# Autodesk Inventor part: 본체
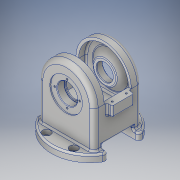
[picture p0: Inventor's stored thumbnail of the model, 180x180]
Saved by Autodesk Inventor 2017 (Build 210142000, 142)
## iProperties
Part Number: 본체
Material: 알루미늄 6061
Document SubType Name: Modeling
Designer: MRC
Density: 2.7 g/cm^3
Appearance: 알루미늄 - 평지
Mass: 1198.45 g
Surface Area: 1058.11 cm^2
Volume: 443.871 cm^3
Author: MRC
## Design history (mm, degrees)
sketch "스케치1"
  geometry: C1 r 71 at (0, 0); 1 further point
  constraints: 1 centre point, 1 coincident
  dimensions: "d0" = 142 diameter of C1
extrude "돌출1" new body sketch "스케치1" distance "d1" = 13; taper "d2" = 0 deg
sketch "스케치2"
  geometry: L1 (-71, 0)-(71, 0) reference; L2 (-51, 81)-(-51, 0); L3 (51, 81)-(51, 0); L4 (-51, 0)-(51, 0); A1 r 51 centre (0, 81) between (-51, 81) and (51, 81); 1 further point
  constraints: 6 end point, 2 point on circle, 2 point on line, 2 tangent, 1 centre point, 1 horizontal, 1 parallel, 1 perpendicular, 1 vertical alignment
  dimensions: "d3" = 102 diameter of A1; "d4" = 81 distance from line of A1.centre L1
extrude "돌출2" join sketch "스케치2" stored distance "d5" = 88; taper "d6" = 0 deg
node "작업 평면1"
sketch "스케치4"
  geometry: L1 (61, -20)-(-61, -20); L2 (-61, -20)-(-61, 20); L3 (-61, 20)-(61, 20); L4 (61, 20)-(61, -20); L5 (61, -20)-(-61, 20); L6 (-61, -20)-(61, 20); 1 further point
  constraints: 12 end point, 2 midpoint, 2 parallel, 1 horizontal, 1 perpendicular
  dimensions: "d10" = 40 distance of L3.end L1.start; "d11" = 122 distance of L1.start L1.end
extrude "돌출3" join sketch "스케치4" distance "d12" = 20; taper "d13" = 0 deg
sketch "스케치5"
  geometry: L1 (-89.487, -28)-(89.487, -28); L2 (89.487, -28)-(89.487, 28); L3 (89.487, 28)-(-89.487, 28); L4 (-89.487, 28)-(-89.487, -28); L5 (-89.487, -28)-(89.487, 28); L6 (89.487, -28)-(-89.487, 28); 1 further point
  constraints: 12 end point, 2 midpoint, 2 parallel, 1 horizontal, 1 perpendicular
  dimensions: "d14" = 56 distance of L1.end L2.end; "d15" = 178.97487 distance of L2.end L3.end
extrude "돌출4" cut sketch "스케치5" distance "d16" = 19; taper "d17" = 0 deg
sketch "스케치6"
  geometry: L1 (-51, 13)-(51, 13) reference; L2 (-51, 13)-(-51, 81) reference; L3 (51, 81)-(51, 13) reference; L4 (-46, 81)-(-46, 40); L5 (46, 40)-(46, 81); L6 (65.246, 0)-(-65.246, 0) reference; L7 (-46, 40)-(46, 40); A1 r 51 centre (0, 81) between (51, 81) and (-51, 81) reference; A2 r 46 centre (0, 81) between (46, 81) and (-46, 81); 1 further point
  constraints: 6 end point, 2 point on circle, 1 centre point, 1 horizontal
  dimensions: "d18" = 5 radial gap between concentric circles of A1 A2; "d20" = 5 distance between parallel lines of L3 L5; "d21" = 5 distance between parallel lines of L2 L4; "d22" = 40 distance between parallel lines of L6 L7
extrude "돌출5" cut sketch "스케치6" stored distance "d23" = 78; taper "d24" = 0 deg
sketch "스케치7"
  geometry: L1 (201.818, -25)-(81, -25); L2 (81, -25)-(81, 25); L3 (81, 25)-(201.818, 25); L4 (201.818, 25)-(201.818, -25); L5 (0, 71)-(0, 28) reference; 2 further points
  constraints: 8 end point, 2 parallel, 1 horizontal, 1 horizontal alignment, 1 midpoint, 1 perpendicular
  dimensions: "d25" = 50 distance of L3.end L1.start; "d26" = 81 distance between parallel lines of L2 L5; "d27" = 120.81817 distance of L2.end L3.end
extrude "돌출6" cut sketch "스케치7" stored distance "d28" = 78; taper "d29" = 0 deg
sketch "스케치8"
  geometry: L1 (81, -25)-(81, 25) reference; L2 (81, -44)-(81, -25) reference; L3 (13, 44)-(81, 44) reference; L4 (81, -44)-(13, -44) reference; L5 (81, -44)-(132, -44) reference; L6 (132, 44)-(81, 44) reference; L7 (81, 25)-(81, 39) reference; L8 (81, -44)-(81, 44); L9 (102.5, -27)-(81, -27); L10 (81, -39)-(127, -39) reference; L11 (102.5, -27)-(114.5, -39); L12 (81, -39)-(114.5, -39); L13 (127, -39)-(127, -25) reference; L14 (81, -39)-(40, -39) reference; L15 (81, -39)-(81, -27); 1 further point
  constraints: 10 end point, 2 point on line, 1 collinear, 1 horizontal, 1 perpendicular, 1 vertical
  dimensions: "d30" = 12 horizontal distance of L9.start L11.end; "d31" = 45 deg angle of L11 L13; "d32" = 67 diameter of L11.end L2
revolve "회전1" sketch "스케치8" stored, may be unused: angle "d33" = 90 deg
sketch "스케치9"
  geometry: L1 (-65.246, 0)-(65.246, 0) reference; C1 r 30 at (0, 81); 2 further points
  constraints: 1 centre point, 1 midpoint, 1 vertical alignment
  dimensions: "d34" = 60 diameter of C1; "d35" = 81 distance from line of C1.centre L1
extrude "돌출7" cut sketch "스케치9" distance "d36" = 2; taper "d37" = 0 deg
sketch "스케치10"
  geometry: C1 r 30 at (0, 0) reference; C2 r 21.5 at (0, 0) reference; C3 r 18.5 at (0, 0); 1 further point
  constraints: 1 centre point, 1 coincident
  dimensions: "d38" = 37 diameter of C3
extrude "돌출8" cut sketch "스케치10" distance "d39" = 13; taper "d40" = 0 deg
sketch "스케치11"
  geometry: C1 r 30 at (0, 0) reference; C2 r 16 at (0, 0); 1 further point
  constraints: 1 centre point, 1 coincident
  dimensions: "d41" = 32 diameter of C2
extrude "돌출9" cut sketch "스케치11" distance "d42" = 13; taper "d43" = 0 deg
sketch "스케치12"
  geometry: C1 r 16 at (0, 0) reference; A1 r 23 centre (0, 0) between (23, 0) and (0, 23); 3 further points
  constraints: 4 point on circle, 2 horizontal alignment, 2 vertical alignment, 1 centre point, 1 coincident
  dimensions: "d44" = 46 diameter of A1
hole "구멍1" sketch "스케치12" at (23, 0), (0, 23), (-23, 0), (0, -23) diameter "d45" = 3.242; stored, may be unused: countersink angle "d49" = 90 deg, drill point angle "d51" = 118 deg; dims "d46" = 8, "d47" = 4, "d48" = 2, "d50" = 10
sketch "스케치13"
  geometry: L1 (54, 13)-(-54, 13); L2 (-54, 13)-(-54, -13); L3 (-54, -13)-(54, -13); L4 (54, -13)-(54, 13); L5 (54, 13)-(-54, -13); L6 (-54, 13)-(54, -13); 5 further points
  constraints: 12 end point, 4 coincident, 2 midpoint, 2 parallel, 1 horizontal, 1 perpendicular
  dimensions: "d52" = 26 distance of L3.end L1.start; "d53" = 108 distance of L2.end L3.end
hole "구멍2" sketch "스케치13" at (54, 13), (54, -13), (-54, -13), (-54, 13) diameter "d54" = 3.242; stored, may be unused: countersink angle "d58" = 90 deg, drill point angle "d60" = 118 deg; dims "d55" = 8, "d56" = 4, "d57" = 2, "d59" = 10
sketch "스케치15"
  geometry: C1 r 30 at (0, 0); 1 further point
  constraints: 1 centre point, 1 coincident
  dimensions: "d69" = 60 diameter of C1
extrude "돌출10" cut sketch "스케치15" distance "d70" = 22; taper "d71" = 0 deg
sketch "스케치16"
  geometry: C1 r 14 at (0, 0); 1 further point
  constraints: 1 centre point, 1 coincident
  dimensions: "d72" = 28 diameter of C1
extrude "돌출11" cut sketch "스케치16" distance "d73" = 15; taper "d74" = 0 deg
sketch "스케치17"
  geometry: C1 r 11 at (0, 0); 1 further point
  constraints: 1 centre point, 1 coincident
  dimensions: "d75" = 22 diameter of C1
extrude "돌출12" cut sketch "스케치17" stored distance "d76" = 15; taper "d77" = 0 deg
sketch "스케치18"
  geometry: A1 r 23 centre (0, 0) between (23, 0) and (0, 23); 3 further points
  constraints: 4 point on circle, 2 horizontal alignment, 2 vertical alignment, 1 centre point, 1 coincident
  dimensions: "d78" = 46 diameter of A1
hole "구멍4" sketch "스케치18" at (23, 0), (0, 23), (-23, 0), (0, -23) diameter "d79" = 3.242; stored, may be unused: countersink angle "d83" = 90 deg, drill point angle "d85" = 118 deg; dims "d80" = 8, "d81" = 4, "d82" = 2, "d84" = 10
sketch "스케치19"
  geometry: L1 (25, 55)-(-25, 55); L2 (-25, 55)-(-25, -55); L3 (-25, -55)-(25, -55); L4 (25, -55)-(25, 55); L5 (25, 55)-(-25, -55); L6 (-25, 55)-(25, -55); 5 further points
  constraints: 12 end point, 4 coincident, 2 midpoint, 2 parallel, 1 horizontal, 1 perpendicular
  dimensions: "d86" = 110 distance of L3.end L1.start; "d87" = 50 distance of L2.end L3.end
hole "구멍5" sketch "스케치19" at (25, 55), (-25, 55), (-25, -55), (25, -55) diameter "d88" = 9; stored, may be unused: countersink angle "d92" = 90 deg, drill point angle "d94" = 118 deg; dims "d89" = 8, "d90" = 15, "d91" = 8.8, "d93" = 10
sketch "스케치20"
  geometry: L1 (-65.246, 0)-(65.246, 0) reference; 3 further points
  constraints: 1 midpoint, 1 vertical alignment, 1 other
  dimensions: "d95" = 30 distance from line of point (0, 30) L1
feature "엠보싱1" sketch "스케치20" dims "d0" = 142, "d96" = 0.5, "d97" = 0
fillet "모깎기1" dims "d98" = 8
fillet "모깎기2" dims "d99" = 6
fillet "모깎기3" dims "d100" = 3
fillet "모깎기4" dims "d101" = 3
fillet "모깎기5" dims "d102" = 3
fillet "모깎기6" dims "d103" = 3
fillet "모깎기7" dims "d104" = 3
chamfer "모따기1" distance "d105" = 1; stored, may be unused: second distance "d106" = 2, angle "d107" = 45 deg
fillet "모깎기8" dims "d108" = 0.3
fillet "모깎기9" dims "d109" = 3
fillet "모깎기10" dims "d110" = 3
node "솔리드1"
mirror "미러1"
mirror "미러2"
mirror "미러3"
node "투영된 루프1"
other parameters: "d9" = 81
